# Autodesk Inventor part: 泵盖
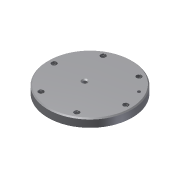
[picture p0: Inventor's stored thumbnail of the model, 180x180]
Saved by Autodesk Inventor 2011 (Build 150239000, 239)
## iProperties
Created: 2013-12
Part Number: 泵盖
Document SubType Name: Modeling
Designer: Administrator
Density: 1 g/cm^3
Author: Administrator
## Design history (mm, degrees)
sketch "草图1"
  geometry: C1 r 41 at (0, 0); 1 further point
  constraints: 1 centre point, 1 coincident
  dimensions: "d0" = 82 diameter of C1
extrude "拉伸1" new body sketch "草图1" distance "d1" = 8; taper "d2" = 0 deg
sketch "草图2"
  geometry: C1 r 41 at (0, 0) reference; C2 r 24 at (0, 0)
  constraints: 1 centre point, 1 coincident
  dimensions: "d3" = 48 diameter of C2
extrude "拉伸2" join sketch "草图2" distance "d4" = 2; taper "d5" = 0 deg
sketch "草图3"
  geometry: C1 r 41 at (0, 0) reference; 1 further point
  dimensions: "d6" = 35 distance of C1.centre point (-35, 0)
hole "Hole1" sketch "草图3" at (-35, 0) diameter "d7" = 4.917; stored, may be unused: countersink angle "d11" = 90 deg, drill point angle "d13" = 118 deg; dims "d8" = 6, "d9" = 4, "d10" = 2, "d12" = 8
pattern_circular "环形阵列1" dims angle "d15" = 360 deg
chamfer "倒角1" distance "d17" = 1; stored, may be unused: second distance "d18" = 2, angle "d19" = 45 deg
sketch "草图4"
  geometry: C1 r 40 at (0, 0) reference; 1 further point
  dimensions: "d20" = 5 distance of C1.centre point (-5, 0)
hole "Hole2" sketch "草图4" at (-5, 0) diameter "d21" = 4; stored, may be unused: countersink angle "d25" = 90 deg, drill point angle "d27" = 118 deg; dims "d22" = 6, "d23" = 6, "d24" = 2, "d26" = 8
sketch "草图5"
  geometry: 1 further point
hole "Hole3" sketch "草图5" at (30.311, 17.5) diameter "d29" = 3; stored, may be unused: countersink angle "d33" = 90 deg, drill point angle "d35" = 118 deg; dims "d30" = 6, "d31" = 6, "d32" = 2, "d34" = 8
node "实体1"
node "工作轴1"
node "工作轴2"
node "工作轴3"
node "工作轴4"
node "工作轴5"
